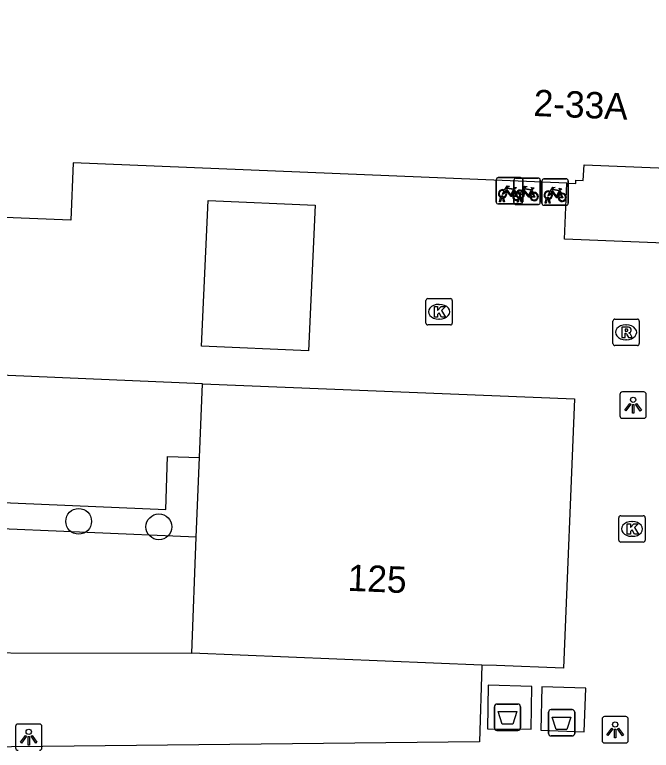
# Model space of a CAD drawing. Extents: x 160891 to 161384, y 386490 to 386907.
# Drawn here: x 161181.11 to 161205.21, y 386520.01 to 386547.89 of the extents above; entities that cross this region are included whole.
import ezdxf

# ---------------------------------------------------------------- set-up
doc = ezdxf.new("R2010")
doc.units = 0
for name, color, linetype in [('IMGEO_Afval_apart_plaats', 7, 'Continuous'), ('IMGEO_Boom', 7, 'Continuous'), ('IMGEO_Fietsenrek', 7, 'Continuous'), ('IMGEO_Groenvoorziening', 7, 'Continuous'), ('IMGEO_Haag', 7, 'Continuous'), ('IMGEO_Kolk', 7, 'Continuous'), ('IMGEO_Lichtpunt', 7, 'Continuous'), ('IMGEO_Pand', 7, 'Continuous'), ('IMGEO_Pand_nummerreeks', 7, 'Continuous'), ('IMGEO_Parkeervlak_open', 7, 'Continuous'), ('IMGEO_Rijbaan_lokaal_open', 7, 'Continuous'), ('IMGEO_Rioolput', 7, 'Continuous'), ('IMGEO_Voetgangersgebied_open', 7, 'Continuous'), ('IMGEO_Voetpad_gesloten', 7, 'Continuous')]:
    doc.layers.add(name, color=color, linetype=linetype)

msp = doc.modelspace()

# ---------------------------------------------------------------- linework, layer by layer
at = {"layer": 'IMGEO_Afval_apart_plaats'}
for p, q in [((161199.27, 386520.86), (161199.27, 386521.66)), ((161199.27, 386521.66), (161199.27, 386520.86)), ((161199.37, 386521.76), (161200.16, 386521.76)), ((161200.16, 386521.76), (161199.37, 386521.76)), ((161200.26, 386521.66), (161200.26, 386520.86)), ((161200.26, 386520.86), (161200.26, 386521.66)), ((161201.423, 386521.55), (161202.213, 386521.55)), ((161202.213, 386521.55), (161201.423, 386521.55)), ((161201.323, 386520.65), (161201.323, 386521.45)), ((161201.323, 386521.45), (161201.323, 386520.65)), ((161202.313, 386521.45), (161202.313, 386520.65)), ((161202.313, 386520.65), (161202.313, 386521.45)), ((161200.16, 386520.76), (161199.37, 386520.76)), ((161199.37, 386520.76), (161200.16, 386520.76)), ((161202.213, 386520.55), (161201.423, 386520.55)), ((161201.423, 386520.55), (161202.213, 386520.55))]:
    msp.add_line(p, q, dxfattribs=at)
for points in [[(161199.413, 386521.474), (161200.117, 386521.474), (161199.968, 386521.004), (161199.562, 386521.004), (161199.413, 386521.474)], [(161201.466, 386521.264), (161202.17, 386521.264), (161202.021, 386520.794), (161201.615, 386520.794), (161201.466, 386521.264)]]:
    msp.add_lwpolyline(points, dxfattribs=at)
for centre, start, end in [((161199.37, 386521.66), 90, 180), ((161199.37, 386521.66), 90, 180), ((161200.16, 386521.66), 0, 90), ((161200.16, 386521.66), 360, 90), ((161201.423, 386521.45), 90, 180), ((161201.423, 386521.45), 90, 180), ((161202.213, 386521.45), 0, 90), ((161202.213, 386521.45), 360, 90), ((161199.37, 386520.86), 180, 270), ((161199.37, 386520.86), 180, 270), ((161200.16, 386520.86), 270, 0), ((161200.16, 386520.86), 270, 0), ((161201.423, 386520.65), 180, 270), ((161201.423, 386520.65), 180, 270), ((161202.213, 386520.65), 270, 0), ((161202.213, 386520.65), 270, 0)]:
    msp.add_arc(centre, 0.1, start, end, dxfattribs=at)
at = {"layer": 'IMGEO_Boom'}
for centre in [(161183.527, 386528.686), (161186.565, 386528.479)]:
    msp.add_circle(centre, 0.489, dxfattribs=at)
at = {"layer": 'IMGEO_Fietsenrek'}
for p, q in [((161199.343, 386540.791), (161199.343, 386541.632)), ((161199.343, 386541.632), (161199.343, 386540.791)), ((161199.418, 386541.716), (161200.259, 386541.716)), ((161200.259, 386541.716), (161199.418, 386541.716)), ((161200.011, 386540.772), (161200.011, 386541.613)), ((161200.011, 386541.613), (161200.011, 386540.772)), ((161200.086, 386541.697), (161200.927, 386541.697)), ((161200.927, 386541.697), (161200.086, 386541.697)), ((161200.343, 386541.641), (161200.343, 386540.8)), ((161200.343, 386540.8), (161200.343, 386541.641)), ((161201.011, 386541.622), (161201.011, 386540.781)), ((161201.011, 386540.781), (161201.011, 386541.622)), ((161201.147, 386541.668), (161201.988, 386541.668)), ((161201.988, 386541.668), (161201.147, 386541.668)), ((161202.072, 386541.593), (161202.072, 386540.752)), ((161202.072, 386540.752), (161202.072, 386541.593)), ((161201.072, 386540.743), (161201.072, 386541.584)), ((161201.072, 386541.584), (161201.072, 386540.743)), ((161200.03, 386541.265), (161200.066, 386541.17)), ((161200.698, 386541.246), (161200.734, 386541.151)), ((161201.759, 386541.217), (161201.795, 386541.122)), ((161199.47, 386540.8), (161199.509, 386540.96)), ((161199.504, 386540.8), (161199.47, 386540.8)), ((161199.539, 386540.948), (161199.504, 386540.8)), ((161199.581, 386540.972), (161199.58, 386540.976)), ((161199.622, 386540.8), (161199.588, 386540.942)), ((161199.612, 386540.983), (161199.613, 386540.976)), ((161199.62, 386540.946), (161199.655, 386540.8)), ((161199.655, 386540.8), (161199.622, 386540.8)), ((161200.138, 386540.781), (161200.177, 386540.941)), ((161200.172, 386540.781), (161200.138, 386540.781)), ((161200.207, 386540.929), (161200.172, 386540.781)), ((161200.249, 386540.953), (161200.248, 386540.957)), ((161200.29, 386540.781), (161200.256, 386540.923)), ((161200.28, 386540.964), (161200.281, 386540.957)), ((161200.288, 386540.927), (161200.323, 386540.781)), ((161200.323, 386540.781), (161200.29, 386540.781)), ((161201.199, 386540.752), (161201.238, 386540.912)), ((161201.268, 386540.9), (161201.233, 386540.752)), ((161201.31, 386540.924), (161201.309, 386540.928)), ((161201.351, 386540.752), (161201.317, 386540.894)), ((161201.341, 386540.935), (161201.342, 386540.928)), ((161201.349, 386540.898), (161201.384, 386540.752)), ((161200.268, 386540.716), (161199.427, 386540.716)), ((161199.427, 386540.716), (161200.268, 386540.716)), ((161200.936, 386540.697), (161200.095, 386540.697)), ((161200.095, 386540.697), (161200.936, 386540.697)), ((161201.997, 386540.668), (161201.156, 386540.668)), ((161201.156, 386540.668), (161201.997, 386540.668)), ((161201.233, 386540.752), (161201.199, 386540.752)), ((161201.384, 386540.752), (161201.351, 386540.752))]:
    msp.add_line(p, q, dxfattribs=at)
for points in [[(161199.656, 386541.242), (161199.751, 386541.406), (161199.837, 386541.392), (161199.839, 386541.383), (161199.783, 386541.372), (161199.756, 386541.327), (161200.012, 386541.286)], [(161200.012, 386541.286), (161200.037, 386541.335), (161200.031, 386541.339), (161200.008, 386541.343), (161199.996, 386541.35), (161199.995, 386541.353), (161199.997, 386541.358), (161200.092, 386541.343), (161200.094, 386541.333), (161200.084, 386541.32), (161200.072, 386541.314), (161200.058, 386541.32), (161200.03, 386541.265)], [(161200.324, 386541.223), (161200.419, 386541.387), (161200.505, 386541.373), (161200.507, 386541.364), (161200.451, 386541.353), (161200.424, 386541.308), (161200.68, 386541.267)], [(161200.68, 386541.267), (161200.705, 386541.316), (161200.699, 386541.32), (161200.676, 386541.324), (161200.664, 386541.331), (161200.663, 386541.334), (161200.665, 386541.339), (161200.76, 386541.324), (161200.762, 386541.314), (161200.752, 386541.301), (161200.74, 386541.295), (161200.726, 386541.301), (161200.698, 386541.246)], [(161201.385, 386541.194), (161201.48, 386541.358), (161201.566, 386541.344), (161201.568, 386541.335), (161201.512, 386541.324), (161201.485, 386541.279), (161201.741, 386541.238)], [(161199.677, 386541.19), (161199.625, 386541.1), (161199.585, 386541.075), (161199.586, 386541.122), (161199.641, 386541.216)], [(161199.952, 386540.998), (161199.902, 386540.998), (161199.711, 386541.249), (161199.692, 386541.217)], [(161199.999, 386541.261), (161199.742, 386541.302), (161199.725, 386541.273), (161199.892, 386541.053), (161199.999, 386541.261)], [(161200.047, 386541.163), (161200.017, 386541.24), (161199.908, 386541.022), (161199.951, 386541.022)], [(161199.981, 386541.022), (161200.101, 386541.021), (161200.057, 386541.135)], [(161200.077, 386541.142), (161200.132, 386540.997), (161199.982, 386540.997)], [(161200.345, 386541.171), (161200.293, 386541.081), (161200.253, 386541.056), (161200.254, 386541.103), (161200.309, 386541.197)], [(161200.62, 386540.979), (161200.57, 386540.979), (161200.379, 386541.23), (161200.36, 386541.198)], [(161200.667, 386541.242), (161200.41, 386541.283), (161200.393, 386541.254), (161200.56, 386541.034), (161200.667, 386541.242)], [(161200.715, 386541.144), (161200.685, 386541.221), (161200.576, 386541.003), (161200.619, 386541.003)], [(161200.649, 386541.003), (161200.769, 386541.002), (161200.725, 386541.116)], [(161200.745, 386541.123), (161200.8, 386540.978), (161200.65, 386540.978)], [(161201.406, 386541.142), (161201.354, 386541.052), (161201.314, 386541.027), (161201.315, 386541.074), (161201.37, 386541.168)], [(161201.681, 386540.95), (161201.631, 386540.95), (161201.44, 386541.201), (161201.421, 386541.169)], [(161201.728, 386541.213), (161201.471, 386541.254), (161201.454, 386541.225), (161201.621, 386541.005), (161201.728, 386541.213)], [(161201.776, 386541.115), (161201.746, 386541.192), (161201.637, 386540.974), (161201.68, 386540.974)], [(161201.71, 386540.974), (161201.83, 386540.973), (161201.786, 386541.087)], [(161201.806, 386541.094), (161201.861, 386540.949), (161201.711, 386540.949)], [(161201.741, 386541.238), (161201.766, 386541.287), (161201.76, 386541.291), (161201.737, 386541.295), (161201.725, 386541.302), (161201.724, 386541.305), (161201.726, 386541.31), (161201.821, 386541.295), (161201.823, 386541.285), (161201.813, 386541.272), (161201.801, 386541.266), (161201.787, 386541.272), (161201.759, 386541.217)]]:
    msp.add_lwpolyline(points, dxfattribs=at)
for centre, radius, start, end in [((161199.421, 386541.638), 0.0779, 92.4484, 184.2845), ((161199.421, 386541.638), 0.0779, 92.4484, 184.2845), ((161200.089, 386541.619), 0.0779, 92.4484, 184.2845), ((161200.089, 386541.619), 0.0779, 92.4484, 184.2845), ((161200.265, 386541.638), 0.0779, 2.4484, 94.2845), ((161200.265, 386541.638), 0.0779, 2.4484, 94.2845), ((161200.933, 386541.619), 0.0779, 2.4484, 94.2845), ((161200.933, 386541.619), 0.0779, 2.4484, 94.2845), ((161201.15, 386541.59), 0.0779, 92.4484, 184.2845), ((161201.15, 386541.59), 0.0779, 92.4484, 184.2845), ((161201.994, 386541.59), 0.0779, 2.4484, 94.2845), ((161201.994, 386541.59), 0.0779, 2.4484, 94.2845), ((161199.583, 386541.101), 0.159, 62.6766, 242.1369), ((161199.583, 386541.101), 0.129, 63.3192, 238.903), ((161199.583, 386541.101), 0.129, 283.6043, 43.4302), ((161199.583, 386541.101), 0.159, 283.5766, 46.6042), ((161200.11, 386541.017), 0.159, 113.3408, 178.3217), ((161200.11, 386541.017), 0.159, 187.0065, 105.7708), ((161200.11, 386541.017), 0.129, 113.923, 177.9556), ((161200.11, 386541.017), 0.129, 188.6715, 104.5883), ((161200.251, 386541.082), 0.159, 62.6766, 242.1369), ((161200.251, 386541.082), 0.129, 63.3192, 238.903), ((161200.251, 386541.082), 0.129, 283.6043, 43.4302), ((161200.251, 386541.082), 0.159, 283.5766, 46.6042), ((161200.778, 386540.998), 0.159, 113.3408, 178.3217), ((161200.778, 386540.998), 0.159, 187.0065, 105.7708), ((161200.778, 386540.998), 0.129, 113.923, 177.9556), ((161200.778, 386540.998), 0.129, 188.6715, 104.5883), ((161201.312, 386541.053), 0.159, 62.6766, 242.1369), ((161201.312, 386541.053), 0.129, 63.3192, 238.903), ((161201.312, 386541.053), 0.129, 283.6043, 43.4302), ((161201.312, 386541.053), 0.159, 283.5766, 46.6042), ((161201.839, 386540.969), 0.159, 113.3408, 178.3217), ((161201.839, 386540.969), 0.159, 187.0065, 105.7708), ((161201.839, 386540.969), 0.129, 113.923, 177.9556), ((161201.839, 386540.969), 0.129, 188.6715, 104.5883), ((161199.421, 386540.794), 0.0779, 182.4484, 274.2845), ((161199.421, 386540.794), 0.0779, 182.4484, 274.2845), ((161199.563, 386540.972), 0.0499, 12.8025, 158.6934), ((161199.583, 386541.101), 0.159, 253.9967, 271.7867), ((161199.563, 386540.972), 0.0174, 12.8025, 163.4502), ((161199.583, 386541.101), 0.129, 253.415, 269.0204), ((161200.089, 386540.775), 0.0779, 182.4484, 274.2845), ((161200.089, 386540.775), 0.0779, 182.4484, 274.2845), ((161200.231, 386540.953), 0.0499, 12.8025, 158.6934), ((161200.251, 386541.082), 0.159, 253.9967, 271.7867), ((161200.231, 386540.953), 0.0174, 12.8025, 163.4502), ((161200.251, 386541.082), 0.129, 253.415, 269.0204), ((161200.265, 386540.794), 0.0779, 272.4484, 4.2845), ((161200.265, 386540.794), 0.0779, 272.4484, 4.2845), ((161200.933, 386540.775), 0.0779, 272.4484, 4.2845), ((161200.933, 386540.775), 0.0779, 272.4484, 4.2845), ((161201.292, 386540.924), 0.0499, 12.8025, 158.6934), ((161201.312, 386541.053), 0.159, 253.9967, 271.7867), ((161201.292, 386540.924), 0.0174, 12.8025, 163.4502), ((161201.312, 386541.053), 0.129, 253.415, 269.0204), ((161201.15, 386540.746), 0.0779, 182.4484, 274.2845), ((161201.15, 386540.746), 0.0779, 182.4484, 274.2845), ((161201.994, 386540.746), 0.0779, 272.4484, 4.2845), ((161201.994, 386540.746), 0.0779, 272.4484, 4.2845)]:
    msp.add_arc(centre, radius, start, end, dxfattribs=at)
at = {"layer": 'IMGEO_Groenvoorziening'}
msp.add_lwpolyline([(161174.072, 386523.72), (161187.807, 386523.685)], dxfattribs=at)
at = {"layer": 'IMGEO_Haag'}
msp.add_lwpolyline([(161187.983, 386528.081), (161167.323, 386528.975)], dxfattribs=at)
at = {"layer": 'IMGEO_Kolk'}
for p, q in [((161196.752, 386537.13), (161197.604, 386537.13)), ((161196.677, 386536.204), (161196.677, 386537.056)), ((161197.165, 386536.91), (161197.19, 386536.91)), ((161197.678, 386537.056), (161197.678, 386536.204)), ((161197.188, 386536.35), (161197.163, 386536.35)), ((161197.604, 386536.13), (161196.752, 386536.13)), ((161203.984, 386527.972), (161203.984, 386528.824)), ((161204.059, 386528.898), (161204.911, 386528.898)), ((161204.985, 386528.824), (161204.985, 386527.972)), ((161204.472, 386528.678), (161204.497, 386528.678)), ((161204.495, 386528.118), (161204.47, 386528.118)), ((161204.911, 386527.898), (161204.059, 386527.898))]:
    msp.add_line(p, q, dxfattribs=at)
for points in [[(161196.752, 386537.13), (161197.604, 386537.13)], [(161196.677, 386536.204), (161196.677, 386537.056)], [(161197.678, 386537.056), (161197.678, 386536.204)], [(161196.998, 386536.83), (161197.121, 386536.83), (161197.121, 386536.679), (161197.251, 386536.83), (161197.415, 386536.83), (161197.269, 386536.679), (161197.422, 386536.43), (161197.27, 386536.43), (161197.185, 386536.594), (161197.121, 386536.527), (161197.121, 386536.43), (161196.998, 386536.43), (161196.998, 386536.83)], [(161197.604, 386536.13), (161196.752, 386536.13)], [(161203.984, 386527.972), (161203.984, 386528.824)], [(161204.059, 386528.898), (161204.911, 386528.898)], [(161204.985, 386528.824), (161204.985, 386527.972)], [(161204.305, 386528.598), (161204.428, 386528.598), (161204.428, 386528.447), (161204.558, 386528.598), (161204.722, 386528.598), (161204.576, 386528.447), (161204.729, 386528.198), (161204.577, 386528.198), (161204.492, 386528.362), (161204.428, 386528.295), (161204.428, 386528.198), (161204.305, 386528.198), (161204.305, 386528.598)], [(161204.911, 386527.898), (161204.059, 386527.898)]]:
    msp.add_lwpolyline(points, dxfattribs=at)
for centre, start, end in [((161196.754, 386537.054), 91.552, 178.448), ((161196.754, 386537.054), 91.552, 178.448), ((161197.602, 386537.054), 1.552, 88.448), ((161197.602, 386537.054), 1.552, 88.448), ((161196.754, 386536.206), 181.552, 268.448), ((161196.754, 386536.206), 181.552, 268.448), ((161197.602, 386536.206), 271.552, 358.448), ((161197.602, 386536.206), 271.552, 358.448), ((161204.061, 386528.822), 91.552, 178.448), ((161204.061, 386528.822), 91.552, 178.448), ((161204.909, 386528.822), 1.552, 88.448), ((161204.909, 386528.822), 1.552, 88.448), ((161204.061, 386527.974), 181.552, 268.448), ((161204.061, 386527.974), 181.552, 268.448), ((161204.909, 386527.974), 271.552, 358.448), ((161204.909, 386527.974), 271.552, 358.448)]:
    msp.add_arc(centre, 0.0765, start, end, dxfattribs=at)
for centre, major_axis, ratio, start_param, end_param in [((161197.164, 386536.63), (-0.387, 0.002), 0.722429, 4.712389, 7.853982), ((161197.189, 386536.63), (-0.39, 0.002), 0.717154, 1.570796, 4.712389), ((161204.471, 386528.398), (-0.387, 0.002), 0.722429, 4.712389, 7.853982), ((161204.496, 386528.398), (-0.39, 0.002), 0.717154, 1.570796, 4.712389)]:
    msp.add_ellipse(centre, major_axis=major_axis, ratio=ratio, start_param=start_param, end_param=end_param, dxfattribs=at)
at = {"layer": 'IMGEO_Lichtpunt'}
for p, q in [((161204.929, 386533.59), (161204.121, 386533.59)), ((161204.929, 386533.59), (161204.121, 386533.59)), ((161204.027, 386533.495), (161204.027, 386532.688)), ((161204.027, 386533.495), (161204.027, 386532.688)), ((161205.023, 386532.688), (161205.023, 386533.495)), ((161205.023, 386532.688), (161205.023, 386533.495)), ((161204.121, 386532.594), (161204.929, 386532.594)), ((161204.121, 386532.594), (161204.929, 386532.594)), ((161204.25, 386521.283), (161203.442, 386521.283)), ((161204.25, 386521.283), (161203.442, 386521.283)), ((161182.039, 386521.004), (161181.231, 386521.004)), ((161182.039, 386521.004), (161181.231, 386521.004)), ((161203.348, 386521.188), (161203.348, 386520.381)), ((161203.348, 386521.188), (161203.348, 386520.381)), ((161204.344, 386520.381), (161204.344, 386521.188)), ((161204.344, 386520.381), (161204.344, 386521.188)), ((161181.137, 386520.909), (161181.137, 386520.102)), ((161181.137, 386520.909), (161181.137, 386520.102)), ((161182.133, 386520.102), (161182.133, 386520.909)), ((161182.133, 386520.102), (161182.133, 386520.909)), ((161203.442, 386520.287), (161204.25, 386520.287)), ((161203.442, 386520.287), (161204.25, 386520.287))]:
    msp.add_line(p, q, dxfattribs=at)
for points in [[(161204.401, 386533.159), (161204.44, 386533.131), (161204.252, 386532.869), (161204.214, 386532.896), (161204.401, 386533.159)], [(161204.503, 386533.111), (161204.55, 386533.111), (161204.55, 386532.789), (161204.503, 386532.789), (161204.503, 386533.111)], [(161204.613, 386533.131), (161204.651, 386533.158), (161204.838, 386532.896), (161204.799, 386532.868), (161204.613, 386533.131)], [(161203.722, 386520.852), (161203.761, 386520.824), (161203.573, 386520.562), (161203.535, 386520.589), (161203.722, 386520.852)], [(161203.824, 386520.804), (161203.871, 386520.804), (161203.871, 386520.482), (161203.824, 386520.482), (161203.824, 386520.804)], [(161203.934, 386520.824), (161203.972, 386520.851), (161204.159, 386520.589), (161204.12, 386520.561), (161203.934, 386520.824)], [(161181.511, 386520.573), (161181.55, 386520.545), (161181.362, 386520.283), (161181.324, 386520.31), (161181.511, 386520.573)], [(161181.613, 386520.525), (161181.66, 386520.525), (161181.66, 386520.203), (161181.613, 386520.203), (161181.613, 386520.525)], [(161181.723, 386520.545), (161181.761, 386520.572), (161181.948, 386520.31), (161181.909, 386520.282), (161181.723, 386520.545)]]:
    msp.add_lwpolyline(points, dxfattribs=at)
for centre in [(161204.526, 386533.293), (161203.847, 386520.986), (161181.636, 386520.707)]:
    msp.add_circle(centre, 0.0994, dxfattribs=at)
for centre, start, end in [((161204.121, 386533.495), 90, 180), ((161204.121, 386533.495), 90, 180), ((161204.929, 386533.495), 0, 90), ((161204.929, 386533.495), 0, 90), ((161204.121, 386532.688), 180, 270), ((161204.121, 386532.688), 180, 270), ((161204.929, 386532.688), 270, 0), ((161204.929, 386532.688), 270, 360), ((161203.442, 386521.188), 90, 180), ((161203.442, 386521.188), 90, 180), ((161204.25, 386521.188), 0, 90), ((161204.25, 386521.188), 0, 90), ((161181.231, 386520.909), 90, 180), ((161181.231, 386520.909), 90, 180), ((161182.039, 386520.909), 0, 90), ((161182.039, 386520.909), 0, 90), ((161203.442, 386520.381), 180, 270), ((161203.442, 386520.381), 180, 270), ((161204.25, 386520.381), 270, 0), ((161204.25, 386520.381), 270, 360), ((161181.231, 386520.102), 180, 270), ((161181.231, 386520.102), 180, 270), ((161182.039, 386520.102), 270, 0), ((161182.039, 386520.102), 270, 360)]:
    msp.add_arc(centre, 0.0946, start, end, dxfattribs=at)
at = {"layer": 'IMGEO_Pand'}
for points in [[(161202.016, 386541.511), (161183.318, 386542.275), (161183.23, 386540.097), (161161.956, 386540.961), (161144.595, 386541.66), (161143.172, 386541.779), (161142.962, 386541.796), (161141.573, 386541.866), (161142.239, 386558.637), (161198.944, 386556.36), (161203.171, 386556.182), (161204.222, 386556.138), (161265.583, 386553.546), (161265.022, 386539.386), (161265.122, 386539.382), (161265.105, 386538.962), (161255.052, 386539.373), (161255.062, 386539.613), (161240.655, 386540.207), (161240.646, 386539.967), (161226.27, 386540.547), (161207.362, 386541.287)], [(161202.016, 386541.511), (161202.353, 386541.497), (161202.357, 386541.624), (161202.637, 386541.61), (161202.666, 386542.205), (161206.74, 386542.032), (161206.717, 386541.442), (161206.997, 386541.431), (161206.992, 386541.301), (161207.362, 386541.287)], [(161188.104, 386531.103), (161188.216, 386533.895)], [(161188.216, 386533.895), (161202.3, 386533.324), (161201.885, 386523.116), (161199.357, 386523.218), (161198.801, 386523.24)], [(161187.983, 386528.081), (161188.104, 386531.103)], [(161187.807, 386523.685), (161187.983, 386528.081)], [(161198.801, 386523.24), (161187.807, 386523.685)]]:
    msp.add_lwpolyline(points, dxfattribs=at)
at = {"layer": 'IMGEO_Parkeervlak_open'}
for points in [[(161188.216, 386533.895), (161153.751, 386535.376), (161153.546, 386530.566)], [(161153.546, 386530.566), (161186.834, 386529.132), (161186.895, 386531.144), (161188.104, 386531.103)]]:
    msp.add_lwpolyline(points, dxfattribs=at)
at = {"layer": 'IMGEO_Rijbaan_lokaal_open'}
for points in [[(161207.362, 386541.287), (161207.269, 386539.164), (161201.927, 386539.387), (161202.016, 386541.511)], [(161192.235, 386535.149), (161188.185, 386535.33), (161188.431, 386540.847), (161192.481, 386540.666), (161192.235, 386535.149)]]:
    msp.add_lwpolyline(points, dxfattribs=at)
at = {"layer": 'IMGEO_Rioolput'}
for p, q in [((161203.834, 386536.351), (161204.686, 386536.351)), ((161203.759, 386535.425), (161203.759, 386536.277)), ((161204.247, 386536.131), (161204.272, 386536.131)), ((161204.76, 386536.277), (161204.76, 386535.425)), ((161204.27, 386535.571), (161204.245, 386535.571)), ((161204.686, 386535.351), (161203.834, 386535.351))]:
    msp.add_line(p, q, dxfattribs=at)
for points in [[(161203.834, 386536.351), (161204.686, 386536.351)], [(161203.759, 386535.425), (161203.759, 386536.277)], [(161204.348, 386536.049), (161204.096, 386536.051), (161204.096, 386535.651)], [(161204.76, 386536.277), (161204.76, 386535.425)], [(161204.096, 386535.651), (161204.22, 386535.651), (161204.22, 386535.813), (161204.231, 386535.813)], [(161204.274, 386535.97), (161204.22, 386535.97), (161204.22, 386535.889)], [(161204.22, 386535.889), (161204.272, 386535.889)], [(161204.278, 386535.784), (161204.349, 386535.651), (161204.489, 386535.651), (161204.424, 386535.777)], [(161204.686, 386535.351), (161203.834, 386535.351)]]:
    msp.add_lwpolyline(points, dxfattribs=at)
for centre, radius, start, end in [((161203.836, 386536.275), 0.0765, 91.552, 178.448), ((161203.836, 386536.275), 0.0765, 91.552, 178.448), ((161204.684, 386536.275), 0.0765, 1.552, 88.448), ((161204.684, 386536.275), 0.0765, 1.552, 88.448), ((161204.347, 386535.939), 0.109, 350.3612, 89.416), ((161204.23, 386535.76), 0.0533, 26.0293, 88.6989), ((161204.256, 386536.078), 0.19, 274.7715, 282.9687), ((161204.28, 386535.874), 0.0964, 77.0061, 93.1865), ((161204.294, 386535.931), 0.0378, 276.6634, 79.6772), ((161204.345, 386535.939), 0.112, 277.5842, 350.9817), ((161204.329, 386535.724), 0.108, 29.5134, 73.7905), ((161203.836, 386535.427), 0.0765, 181.552, 268.448), ((161203.836, 386535.427), 0.0765, 181.552, 268.448), ((161204.684, 386535.427), 0.0765, 271.552, 358.448), ((161204.684, 386535.427), 0.0765, 271.552, 358.448)]:
    msp.add_arc(centre, radius, start, end, dxfattribs=at)
for centre, major_axis, ratio, start_param, end_param in [((161204.246, 386535.851), (-0.387, 0.002), 0.722429, 4.712389, 7.853982), ((161204.271, 386535.851), (-0.39, 0.002), 0.717154, 1.570796, 4.712389)]:
    msp.add_ellipse(centre, major_axis=major_axis, ratio=ratio, start_param=start_param, end_param=end_param, dxfattribs=at)
at = {"layer": 'IMGEO_Voetgangersgebied_open'}
msp.add_lwpolyline([(161198.801, 386523.24), (161198.713, 386520.334), (161173.891, 386520.061)], dxfattribs=at)
at = {"layer": 'IMGEO_Voetpad_gesloten'}
for points in [[(161199.042, 386522.473), (161199.008, 386520.826), (161200.666, 386520.805), (161200.688, 386522.428), (161199.042, 386522.473)], [(161201.026, 386520.776), (161202.666, 386520.71), (161202.736, 386522.365), (161201.068, 386522.41), (161201.026, 386520.776)]]:
    msp.add_lwpolyline(points, dxfattribs=at)

# ---------------------------------------------------------------- texts
at = {"layer": 'IMGEO_Pand_nummerreeks'}
for s, rotation, p in [('2-33A', 357.7142, (161200.742, 386544.053)), ('125', 357.6738, (161193.7, 386526.055))]:
    msp.add_text(s, height=1, rotation=rotation, dxfattribs=at).set_placement(p)

doc.saveas('drawing.dxf')
